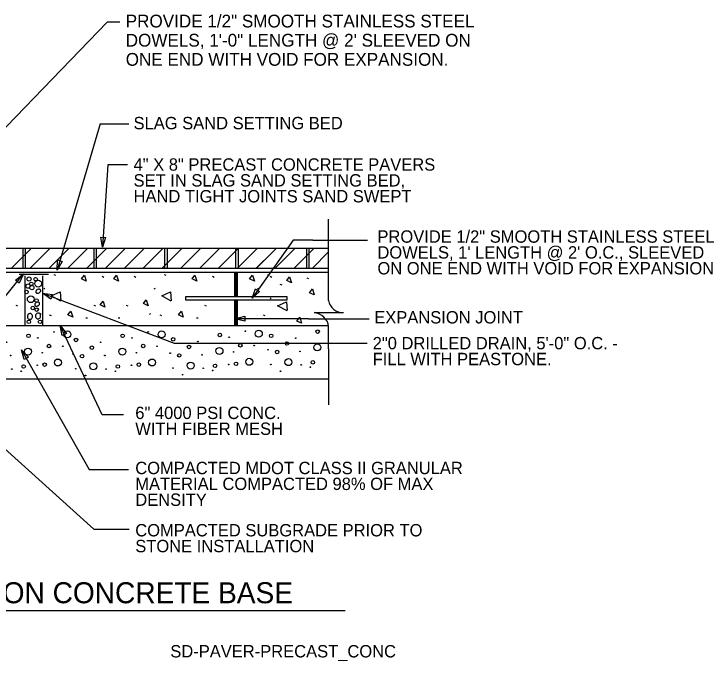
# Model space of a CAD drawing. Extents: x 9881.8 to 9971.9, y 10019.5 to 10074.2.
# Drawn here: x 9912.7 to 9971.9, y 10019.5 to 10074.2 of the extents above; entities that cross this region are included whole.
import ezdxf

# ---------------------------------------------------------------- set-up
doc = ezdxf.new("R2010")
doc.units = 0
for name, color, linetype in [('Default', 7, 'Continuous'), ('G-ANNO-TEXT', 7, 'Continuous'), ('G-ANNO-TTXT', 7, 'Continuous'), ('G-DETL-LINE', 7, 'Continuous'), ('G-DETL-PATT', 7, 'Continuous')]:
    doc.layers.add(name, color=color, linetype=linetype)

# ---------------------------------------------------------------- blocks, each defined once
blk = doc.blocks.new('COMPAC')
at = {"layer": 'Default'}
for centre, radius in [((0.206, -0.126), 0.0273), ((0.938, -0.126), 0.0273), ((1.341, -0.102), 0.00521), ((1.547, -0.16), 0.0546), ((0.586, -0.197), 0.00521), ((1.081, -0.173), 0.00521), ((0.442, -0.268), 0.0273), ((0.91, -0.372), 0.0546), ((1.244, -0.315), 0.0273), ((0.138, -0.338), 0.00521), ((0.277, -0.386), 0.0273), ((0.633, -0.409), 0.00521), ((1.129, -0.409), 0.00521), ((1.459, -0.338), 0.00521), ((0.439, -0.561), 0.0546), ((1.359, -0.584), 0.0546), ((0.161, -0.574), 0.00521), ((0.633, -0.621), 0.00521), ((0.82, -0.598), 0.0273), ((1.034, -0.598), 0.00521), ((1.15, -0.598), 0.0273), ((0.303, -0.692), 0.00521), ((0.775, -0.669), 0.00521)]:
    blk.add_circle(centre, radius, dxfattribs=at)
blk = doc.blocks.new('TERARR')
at = {"layer": 'Default'}
blk.add_lwpolyline([(-0.667, 0.167), (0, 0), (-0.667, -0.167)], close=True, dxfattribs=at)

msp = doc.modelspace()

# ---------------------------------------------------------------- linework, layer by layer
at = {"layer": 'Default'}
for p, q in [((9930.315, 10052.323), (9930.315, 10052.323)), ((9913.641, 10052.183), (9913.641, 10052.183))]:
    msp.add_line(p, q, dxfattribs=at)
msp.add_lwpolyline([(9927.237, 10050.291), (9935.797, 10050.291), (9935.797, 10049.98), (9927.237, 10049.98)], close=True, dxfattribs=at)
at = {"layer": 'G-ANNO-TEXT'}
for p, q in [((9920.601, 10073.485), (9898.154, 10050.244)), ((9921.671, 10073.485), (9920.591, 10073.485)), ((9920.009, 10064.893), (9916.355, 10052.518)), ((9920.009, 10064.893), (9922.419, 10064.893)), ((9920.657, 10061.417), (9920.201, 10054.459)), ((9922.319, 10061.417), (9920.657, 10061.417)), ((9939.318, 10052.046), (9939.318, 10056.816)), ((9936.314, 10055.046), (9932.844, 10050.134)), ((9937.976, 10055.046), (9936.314, 10055.046)), ((9937.976, 10055.046), (9942.604, 10055.046)), ((9939.318, 10049.945), (9939.318, 10052.046)), ((9938.106, 10048.922), (9940.586, 10048.922)), ((9937.63, 10048.406), (9931.396, 10048.406)), ((9937.63, 10048.406), (9942.758, 10048.406)), ((9920.171, 10040.28), (9916.618, 10047.83)), ((9939.318, 10045.873), (9939.318, 10047.748)), ((9940.412, 10046.354), (9942.566, 10046.354)), ((9913.359, 10045.779), (9919.076, 10035.661)), ((9939.318, 10045.873), (9939.318, 10041.127)), ((9908.077, 10040.874), (9919.479, 10030.603)), ((9921.983, 10040.28), (9920.171, 10040.28)), ((9919.076, 10035.661), (9922.398, 10035.661)), ((9919.479, 10030.603), (9922.457, 10030.603)), ((9888.442, 10023.729), (9940.731, 10023.729))]:
    msp.add_line(p, q, dxfattribs=at)
for points in [[(9897.965, 10035.156), (9899.77, 10035.156), (9913.525, 10052.191)], [(9915.115, 10050.564), (9926.267, 10046.354), (9940.412, 10046.354)]]:
    msp.add_lwpolyline(points, dxfattribs=at)
for centre, radius, start, end in [((9940.524, 10050.143), 1.222, 189.31667, 272.89616), ((9937.972, 10047.571), 1.358, 7.50244, 84.36196)]:
    msp.add_arc(centre, radius, start, end, dxfattribs=at)
at = {"layer": 'G-ANNO-TTXT'}
msp.add_line((9913.16, 10052.185), (9915.643, 10052.185), dxfattribs=at)
at = {"layer": 'G-DETL-LINE'}
for p, q in [((9901.665, 10054.383), (9939.318, 10054.383)), ((9913.456, 10054.383), (9913.456, 10052.694)), ((9913.662, 10054.383), (9913.662, 10052.694)), ((9919.455, 10054.383), (9919.455, 10052.694)), ((9919.661, 10054.383), (9919.661, 10052.694)), ((9925.453, 10054.383), (9925.453, 10052.694)), ((9925.66, 10054.383), (9925.66, 10052.694)), ((9931.452, 10054.383), (9931.452, 10052.694)), ((9931.658, 10054.383), (9931.658, 10052.694)), ((9937.451, 10054.383), (9937.451, 10052.694)), ((9937.657, 10054.383), (9937.657, 10052.694)), ((9896.337, 10052.334), (9939.318, 10052.334)), ((9901.665, 10052.694), (9939.318, 10052.694)), ((9931.373, 10052.315), (9931.373, 10050.294)), ((9931.579, 10052.302), (9931.579, 10050.298)), ((9913.641, 10052.047), (9913.641, 10047.83)), ((9915.136, 10052.022), (9915.136, 10047.83)), ((9931.373, 10049.996), (9931.373, 10047.83)), ((9931.579, 10049.997), (9931.579, 10047.83)), ((9901.665, 10047.83), (9913.641, 10047.83)), ((9913.641, 10047.83), (9915.136, 10047.83)), ((9915.136, 10047.83), (9939.318, 10047.83)), ((9891.038, 10043.327), (9939.318, 10043.327))]:
    msp.add_line(p, q, dxfattribs=at)
at = {"layer": 'G-DETL-PATT'}
for p, q in [((9912.501, 10052.694), (9914.19, 10054.383)), ((9914.094, 10052.694), (9915.782, 10054.383)), ((9915.686, 10052.694), (9917.375, 10054.383)), ((9917.278, 10052.694), (9918.966, 10054.383)), ((9918.87, 10052.694), (9920.559, 10054.383)), ((9920.463, 10052.694), (9922.151, 10054.383)), ((9922.055, 10052.694), (9923.744, 10054.383)), ((9923.647, 10052.694), (9925.335, 10054.383)), ((9925.239, 10052.694), (9926.928, 10054.383)), ((9926.832, 10052.694), (9928.52, 10054.383)), ((9928.424, 10052.694), (9930.113, 10054.383)), ((9930.016, 10052.694), (9931.705, 10054.383)), ((9931.608, 10052.694), (9933.297, 10054.383)), ((9933.217, 10052.694), (9934.906, 10054.383)), ((9934.809, 10052.694), (9936.498, 10054.383)), ((9936.402, 10052.694), (9938.091, 10054.383)), ((9937.96, 10052.694), (9939.318, 10054.052)), ((9933.201, 10052.694), (9933.83, 10053.324)), ((9931.427, 10052.29), (9931.427, 10050.299)), ((9931.488, 10052.321), (9931.488, 10050.298)), ((9916.245, 10052.061), (9916.101, 10052.125)), ((9920.305, 10051.901), (9920.161, 10051.966)), ((9923.033, 10051.901), (9922.889, 10051.966)), ((9925.589, 10052.061), (9925.445, 10052.125)), ((9929.649, 10051.901), (9929.505, 10051.966)), ((9934.312, 10052.061), (9934.168, 10052.125)), ((9934.521, 10051.901), (9934.377, 10051.966)), ((9937.658, 10051.768), (9937.514, 10051.832)), ((9935.38, 10051.237), (9935.236, 10051.301)), ((9915.231, 10050.924), (9915.327, 10050.988)), ((9924.574, 10050.924), (9924.67, 10050.988)), ((9933.297, 10050.924), (9933.393, 10050.988)), ((9933.379, 10050.939), (9933.379, 10050.939)), ((9915.53, 10050.359), (9915.53, 10050.359)), ((9931.427, 10049.993), (9931.427, 10047.842)), ((9931.488, 10049.999), (9931.488, 10047.831)), ((9934.366, 10050.1), (9934.462, 10050.164)), ((9913.034, 10049.472), (9912.89, 10049.536)), ((9919.65, 10049.472), (9919.506, 10049.536)), ((9922.378, 10049.472), (9922.234, 10049.536)), ((9928.993, 10049.472), (9928.849, 10049.536)), ((9914.907, 10048.771), (9915.003, 10048.835)), ((9915.877, 10048.65), (9915.733, 10048.714)), ((9924.167, 10048.771), (9924.263, 10048.835)), ((9925.221, 10048.65), (9925.077, 10048.714)), ((9933.944, 10048.65), (9933.8, 10048.714)), ((9918.801, 10048.475), (9918.945, 10048.491)), ((9921.529, 10048.475), (9921.673, 10048.491)), ((9928.145, 10048.475), (9928.289, 10048.491)), ((9933.297, 10048.691), (9933.297, 10048.691))]:
    msp.add_line(p, q, dxfattribs=at)
for points in [[(9931.373, 10052.287), (9931.461, 10052.272), (9931.55, 10052.284), (9931.579, 10052.281)], [(9918.826, 10051.585), (9918.427, 10051.777), (9918.666, 10052.096), (9918.826, 10051.585)], [(9921.554, 10051.585), (9921.155, 10051.777), (9921.394, 10052.096), (9921.554, 10051.585)], [(9928.17, 10051.585), (9927.77, 10051.777), (9928.01, 10052.096), (9928.17, 10051.585)], [(9931.373, 10052.199), (9931.421, 10052.191), (9931.53, 10052.207), (9931.566, 10052.203), (9931.579, 10052.2)], [(9931.373, 10052.146), (9931.461, 10052.109), (9931.497, 10052.101), (9931.542, 10052.098), (9931.579, 10052.095)], [(9931.373, 10052.056), (9931.425, 10052.053), (9931.506, 10052.024), (9931.555, 10052.004), (9931.579, 10051.998)], [(9931.579, 10051.954), (9931.562, 10051.959), (9931.494, 10051.972), (9931.437, 10051.955), (9931.384, 10051.939), (9931.373, 10051.937)], [(9931.373, 10051.876), (9931.44, 10051.894), (9931.546, 10051.923), (9931.579, 10051.923)], [(9931.579, 10051.817), (9931.534, 10051.814), (9931.469, 10051.798), (9931.376, 10051.801), (9931.373, 10051.801)], [(9931.373, 10051.715), (9931.425, 10051.715), (9931.513, 10051.707), (9931.575, 10051.702), (9931.579, 10051.703)], [(9933.042, 10051.585), (9932.642, 10051.777), (9932.882, 10052.096), (9933.042, 10051.585)], [(9936.179, 10051.452), (9935.78, 10051.643), (9936.019, 10051.963), (9936.179, 10051.452)], [(9931.373, 10051.625), (9931.461, 10051.61), (9931.55, 10051.621), (9931.579, 10051.618)], [(9931.373, 10051.536), (9931.421, 10051.528), (9931.53, 10051.545), (9931.566, 10051.54), (9931.579, 10051.537)], [(9931.373, 10051.483), (9931.461, 10051.447), (9931.497, 10051.438), (9931.542, 10051.435), (9931.579, 10051.432)], [(9931.373, 10051.393), (9931.425, 10051.39), (9931.506, 10051.362), (9931.555, 10051.341), (9931.579, 10051.336)], [(9931.579, 10051.291), (9931.562, 10051.297), (9931.494, 10051.309), (9931.437, 10051.292), (9931.384, 10051.276), (9931.373, 10051.275)], [(9931.373, 10051.213), (9931.44, 10051.231), (9931.546, 10051.26), (9931.579, 10051.26)], [(9931.579, 10051.154), (9931.534, 10051.151), (9931.469, 10051.135), (9931.376, 10051.138), (9931.373, 10051.138)], [(9916.676, 10049.903), (9915.861, 10050.335), (9916.612, 10050.671), (9916.676, 10049.919)], [(9926.02, 10049.903), (9925.205, 10050.335), (9925.956, 10050.671), (9926.02, 10049.919)], [(9931.373, 10051.06), (9931.425, 10051.06), (9931.513, 10051.052), (9931.575, 10051.047), (9931.579, 10051.048)], [(9931.373, 10050.97), (9931.461, 10050.955), (9931.55, 10050.966), (9931.579, 10050.963)], [(9931.373, 10050.881), (9931.421, 10050.874), (9931.53, 10050.89), (9931.566, 10050.885), (9931.579, 10050.883)], [(9931.373, 10050.829), (9931.461, 10050.792), (9931.497, 10050.784), (9931.542, 10050.78), (9931.579, 10050.777)], [(9931.373, 10050.739), (9931.425, 10050.735), (9931.506, 10050.707), (9931.555, 10050.686), (9931.579, 10050.681)], [(9931.579, 10050.636), (9931.562, 10050.642), (9931.494, 10050.654), (9931.437, 10050.638), (9931.384, 10050.621), (9931.373, 10050.621)], [(9931.373, 10050.558), (9931.44, 10050.576), (9931.546, 10050.605), (9931.579, 10050.605)], [(9931.373, 10050.522), (9931.461, 10050.506), (9931.55, 10050.518), (9931.579, 10050.514)], [(9938.104, 10050.414), (9937.705, 10050.606), (9937.945, 10050.925), (9938.104, 10050.414)], [(9920.412, 10049.394), (9920.012, 10049.586), (9920.252, 10049.905), (9920.412, 10049.394)], [(9924.056, 10049.504), (9923.656, 10049.696), (9923.896, 10050.015), (9924.056, 10049.504)], [(9931.579, 10050.446), (9931.534, 10050.443), (9931.469, 10050.427), (9931.376, 10050.431), (9931.373, 10050.431)], [(9931.373, 10050.347), (9931.425, 10050.347), (9931.513, 10050.338), (9931.575, 10050.335), (9931.579, 10050.336)], [(9931.373, 10050.318), (9931.461, 10050.303), (9931.55, 10050.314), (9931.579, 10050.311)], [(9931.579, 10049.984), (9931.562, 10049.989), (9931.494, 10050.002), (9931.437, 10049.986), (9931.384, 10049.969), (9931.373, 10049.968)], [(9931.373, 10049.906), (9931.44, 10049.924), (9931.546, 10049.953), (9931.579, 10049.953)], [(9931.579, 10049.847), (9931.534, 10049.844), (9931.469, 10049.828), (9931.376, 10049.832), (9931.373, 10049.832)], [(9931.373, 10049.753), (9931.425, 10049.753), (9931.513, 10049.744), (9931.575, 10049.741), (9931.579, 10049.741)], [(9931.373, 10049.663), (9931.461, 10049.648), (9931.55, 10049.659), (9931.579, 10049.656)], [(9931.373, 10049.574), (9931.421, 10049.566), (9931.53, 10049.583), (9931.566, 10049.578), (9931.579, 10049.576)], [(9931.373, 10049.522), (9931.461, 10049.485), (9931.497, 10049.477), (9931.542, 10049.473), (9931.579, 10049.47)], [(9931.373, 10049.432), (9931.425, 10049.428), (9931.506, 10049.4), (9931.555, 10049.379), (9931.579, 10049.374)], [(9931.579, 10049.329), (9931.562, 10049.335), (9931.494, 10049.347), (9931.437, 10049.331), (9931.384, 10049.315), (9931.373, 10049.314)], [(9931.373, 10049.251), (9931.44, 10049.269), (9931.546, 10049.298), (9931.579, 10049.298)], [(9935.812, 10049.079), (9934.996, 10049.511), (9935.748, 10049.847), (9935.812, 10049.095)], [(9917.683, 10048.538), (9917.284, 10048.729), (9917.524, 10049.049), (9917.683, 10048.538)], [(9927.027, 10048.538), (9926.627, 10048.729), (9926.867, 10049.049), (9927.027, 10048.538)], [(9931.579, 10049.192), (9931.534, 10049.189), (9931.469, 10049.173), (9931.376, 10049.177), (9931.373, 10049.177)], [(9931.373, 10049.079), (9931.425, 10049.079), (9931.513, 10049.071), (9931.575, 10049.067), (9931.579, 10049.069)], [(9931.373, 10048.989), (9931.461, 10048.974), (9931.55, 10048.987), (9931.579, 10048.983)], [(9931.373, 10048.9), (9931.421, 10048.893), (9931.53, 10048.909), (9931.566, 10048.906), (9931.579, 10048.902)], [(9931.373, 10048.849), (9931.461, 10048.812), (9931.497, 10048.804), (9931.542, 10048.799), (9931.579, 10048.797)], [(9931.373, 10048.758), (9931.425, 10048.755), (9931.506, 10048.726), (9931.555, 10048.707), (9931.579, 10048.7)], [(9931.579, 10048.655), (9931.562, 10048.661), (9931.494, 10048.674), (9931.437, 10048.657), (9931.384, 10048.642), (9931.373, 10048.64)], [(9931.373, 10048.579), (9931.44, 10048.597), (9931.546, 10048.625), (9931.579, 10048.625)], [(9931.579, 10048.518), (9931.534, 10048.516), (9931.469, 10048.499), (9931.376, 10048.504), (9931.373, 10048.504)], [(9931.373, 10048.416), (9931.425, 10048.416), (9931.513, 10048.408), (9931.575, 10048.405), (9931.579, 10048.406)], [(9931.373, 10048.326), (9931.461, 10048.311), (9931.55, 10048.324), (9931.579, 10048.32)], [(9931.373, 10048.238), (9931.421, 10048.23), (9931.53, 10048.246), (9931.566, 10048.243), (9931.579, 10048.239)], [(9931.373, 10048.186), (9931.461, 10048.149), (9931.497, 10048.141), (9931.542, 10048.136), (9931.579, 10048.135)], [(9937.038, 10048.021), (9936.638, 10048.213), (9936.878, 10048.532), (9937.038, 10048.021)], [(9931.373, 10048.096), (9931.425, 10048.092), (9931.506, 10048.063), (9931.555, 10048.044), (9931.579, 10048.037)], [(9931.579, 10047.993), (9931.562, 10047.999), (9931.494, 10048.011), (9931.437, 10047.995), (9931.384, 10047.979), (9931.373, 10047.977)], [(9931.373, 10047.916), (9931.44, 10047.934), (9931.546, 10047.963), (9931.579, 10047.963)], [(9931.579, 10047.856), (9931.534, 10047.853), (9931.469, 10047.836), (9931.376, 10047.841), (9931.373, 10047.841)]]:
    msp.add_lwpolyline(points, dxfattribs=at)
for centre, radius in [((9913.994, 10051.766), 0.171), ((9914.548, 10051.747), 0.149), ((9914.764, 10051.375), 0.289), ((9913.9, 10051.167), 0.177), ((9914.183, 10051.352), 0.149), ((9914.23, 10051.04), 0.177), ((9913.774, 10050.67), 0.149), ((9914.135, 10050.058), 0.289), ((9914.622, 10049.954), 0.149), ((9914.308, 10049.307), 0.149), ((9914.638, 10049.18), 0.149), ((9913.978, 10048.139), 0.149), ((9914.921, 10048.139), 0.149), ((9934.456, 10046.959), 0.148), ((9938.393, 10047.314), 0.148), ((9935.795, 10046.312), 0.148), ((9936.535, 10046.764), 0.0281), ((9934.191, 10045.785), 0.0281), ((9934.963, 10045.597), 0.148), ((9938.366, 10045.98), 0.295), ((9936.892, 10045.644), 0.0281), ((9935.918, 10044.735), 0.295), ((9937.987, 10044.717), 0.148), ((9934.433, 10044.526), 0.0281), ((9935.252, 10043.96), 0.0281), ((9936.995, 10044.501), 0.0281), ((9937.78, 10044.316), 0.0281)]:
    msp.add_circle(centre, radius, dxfattribs=at)
for centre, radius, start, end in [((9914.734, 10050.673), 0.173, 151.90902, 176.30838), ((9914.671, 10050.677), 0.11, 176.30838, 207.00223), ((9914.671, 10050.677), 0.11, 207.00223, 237.69608), ((9914.788, 10050.644), 0.235, 133.12323, 151.90902), ((9914.705, 10050.73), 0.173, 237.69608, 262.09544), ((9914.845, 10050.583), 0.319, 117.00223, 133.12323), ((9914.713, 10050.791), 0.235, 262.09544, 280.88123), ((9914.845, 10050.583), 0.319, 100.88123, 117.00223), ((9914.697, 10050.873), 0.319, 280.88123, 297.00223), ((9914.83, 10050.665), 0.235, 82.09544, 100.88123), ((9914.697, 10050.873), 0.319, 297.00223, 313.12323), ((9914.838, 10050.726), 0.173, 57.69608, 82.09544), ((9914.754, 10050.812), 0.235, 313.12323, 331.90902), ((9914.872, 10050.779), 0.11, 27.00223, 57.69608), ((9914.809, 10050.783), 0.173, 331.90902, 356.30838), ((9914.872, 10050.779), 0.11, 356.30838, 27.00223), ((9914.577, 10049.591), 0.11, 176.30838, 207.00223), ((9914.64, 10049.587), 0.173, 151.90902, 176.30838), ((9914.577, 10049.591), 0.11, 207.00223, 237.69608), ((9914.694, 10049.557), 0.235, 133.12323, 151.90902), ((9914.61, 10049.644), 0.173, 237.69608, 262.09544), ((9914.751, 10049.497), 0.319, 117.00223, 133.12323), ((9914.619, 10049.705), 0.235, 262.09544, 280.88123), ((9914.751, 10049.497), 0.319, 100.88123, 117.00223), ((9914.603, 10049.787), 0.319, 280.88123, 297.00223), ((9914.735, 10049.579), 0.235, 82.09544, 100.88123), ((9914.603, 10049.787), 0.319, 297.00223, 313.12323), ((9914.744, 10049.64), 0.173, 57.69608, 82.09544), ((9914.66, 10049.726), 0.235, 313.12323, 331.90902), ((9914.778, 10049.693), 0.11, 27.00223, 57.69608), ((9914.715, 10049.697), 0.173, 331.90902, 356.30838), ((9914.778, 10049.693), 0.11, 356.30838, 27.00223), ((9914.133, 10048.589), 0.286, 154.74697, 174.58429), ((9914.101, 10048.605), 0.25, 133.53014, 154.74697), ((9914.081, 10048.625), 0.222, 110.01957, 133.53014), ((9914.07, 10048.655), 0.19, 84.58429, 110.01957), ((9914.07, 10048.655), 0.19, 59.149, 84.58429), ((9914.054, 10048.628), 0.222, 35.63843, 59.149), ((9914.031, 10048.611), 0.25, 14.42161, 35.63843), ((9914.824, 10048.636), 0.286, 154.74697, 174.58429), ((9914.792, 10048.651), 0.25, 133.53014, 154.74697), ((9914.772, 10048.671), 0.222, 110.01957, 133.53014), ((9914.761, 10048.701), 0.19, 84.58429, 110.01957), ((9914.761, 10048.701), 0.19, 59.149, 84.58429), ((9914.745, 10048.674), 0.222, 35.63843, 59.149), ((9914.722, 10048.657), 0.25, 14.42161, 35.63843), ((9914.687, 10048.649), 0.286, 354.58429, 14.42161), ((9914.133, 10048.589), 0.286, 174.58429, 194.42161), ((9914.099, 10048.581), 0.25, 194.42161, 215.63843), ((9914.076, 10048.564), 0.222, 215.63843, 239.149), ((9914.059, 10048.537), 0.19, 239.149, 264.58429), ((9914.059, 10048.537), 0.19, 264.58429, 290.01957), ((9914.048, 10048.567), 0.222, 290.01957, 313.53014), ((9914.029, 10048.587), 0.25, 313.53014, 334.74697), ((9913.997, 10048.602), 0.286, 334.74697, 354.58429), ((9913.997, 10048.602), 0.286, 354.58429, 14.42161), ((9914.824, 10048.636), 0.286, 174.58429, 194.42161), ((9914.789, 10048.627), 0.25, 194.42161, 215.63843), ((9914.766, 10048.61), 0.222, 215.63843, 239.149), ((9914.75, 10048.583), 0.19, 239.149, 264.58429), ((9914.75, 10048.583), 0.19, 264.58429, 290.01957), ((9914.739, 10048.613), 0.222, 290.01957, 313.53014), ((9914.72, 10048.633), 0.25, 313.53014, 334.74697), ((9914.687, 10048.649), 0.286, 334.74697, 354.58429)]:
    msp.add_arc(centre, radius, start, end, dxfattribs=at)

# ---------------------------------------------------------------- block references
at = {"layer": 'G-ANNO-TEXT'}
for p, xscale, yscale, rotation in [((9920.201, 10054.459), 1.24992, 1.24992, -93.74712904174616), ((9916.355, 10052.518), 1.2499200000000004, 1.2499200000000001, -106.45138457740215), ((9913.525, 10052.191), 1.2499200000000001, 1.24992, 51.08067138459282), ((9915.115, 10050.564), 1.2499200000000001, 1.2499200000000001, 159.31657943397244), ((9932.844, 10050.134), 1.2499200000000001, 1.24992, -123.27882136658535), ((9931.396, 10048.406), 1.24992, 1.24992, 180), ((9916.618, 10047.83), 1.24992, 1.24992, 115.19849005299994), ((9913.359, 10045.779), 1.24992, 1.24992, 119.46782083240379)]:
    msp.add_blockref('TERARR', p, dxfattribs=dict(at, xscale=xscale, yscale=yscale, rotation=rotation))
at = {"layer": 'G-DETL-PATT', "xscale": 5.4043195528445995, "yscale": 5.4043195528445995, "rotation": 5.1522960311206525}
for p in [(9908.831, 10047.189), (9916.794, 10047.189), (9925.011, 10047.248)]:
    msp.add_blockref('COMPAC', p, dxfattribs=at)

# ---------------------------------------------------------------- texts
at = {"layer": 'G-ANNO-TEXT'}
for s, height, p in [('PROVIDE 1/2" SMOOTH STAINLESS STEEL ', 1.08, (9922.163, 10073.038)), ('DOWELS, 1\'-0" LENGTH @ 2\' SLEEVED ON ', 1.08, (9922.163, 10071.418)), ('ONE END WITH VOID FOR EXPANSION.', 1.08, (9922.163, 10069.798)), ('SLAG SAND SETTING BED', 1.044, (9922.826, 10064.428)), ('4" X 8" PRECAST CONCRETE PAVERS', 1.044, (9922.826, 10060.927)), ('SET IN SLAG SAND SETTING BED, ', 1.044, (9922.826, 10059.586)), ('HAND TIGHT JOINTS SAND SWEPT', 1.044, (9922.826, 10058.245)), ('PROVIDE 1/2" SMOOTH STAINLESS STEEL ', 1.044, (9943.446, 10054.836)), ("DOWELS, 1' LENGTH @ 2' O.C., SLEEVED ", 1.044, (9943.446, 10053.495)), ('ON ONE END WITH VOID FOR EXPANSION', 1.044, (9943.446, 10052.154)), ('EXPANSION JOINT', 1.044, (9943.18, 10048.006)), ('2"0 DRILLED DRAIN, 5\'-0" O.C. -', 1.044, (9943.044, 10045.82)), ('FILL WITH PEASTONE.', 1.044, (9943.044, 10044.479)), ('6" 4000 PSI CONC.', 1.044, (9922.972, 10039.924)), ('WITH FIBER MESH', 1.044, (9922.972, 10038.583)), ('COMPACTED MDOT CLASS II GRANULAR', 1.044, (9922.972, 10035.264)), ('MATERIAL COMPACTED 98% OF MAX', 1.044, (9922.972, 10033.923)), ('DENSITY', 1.044, (9922.972, 10032.582)), ('COMPACTED SUBGRADE PRIOR TO', 1.044, (9922.972, 10030.001)), ('STONE INSTALLATION', 1.044, (9922.972, 10028.661)), ('PRECAST PAVER ON CONCRETE BASE', 1.776, (9891.173, 10024.347)), ('SD-PAVER-PRECAST_CONC', 1.044, (9925.935, 10019.765))]:
    msp.add_text(s, height=height, dxfattribs=at).set_placement(p)

doc.saveas('drawing.dxf')
